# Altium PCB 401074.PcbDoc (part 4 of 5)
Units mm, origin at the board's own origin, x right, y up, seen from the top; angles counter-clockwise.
Board outline 70.15 x 35.15 mm, 6 copper layers (Top Layer, Mid-Layer1, Mid-Layer2, Mid-Layer3, Mid-Layer4, Bottom Layer), stack 1.549 mm thick; 239 components, 182 nets, 1034 pads, 1263 vias.
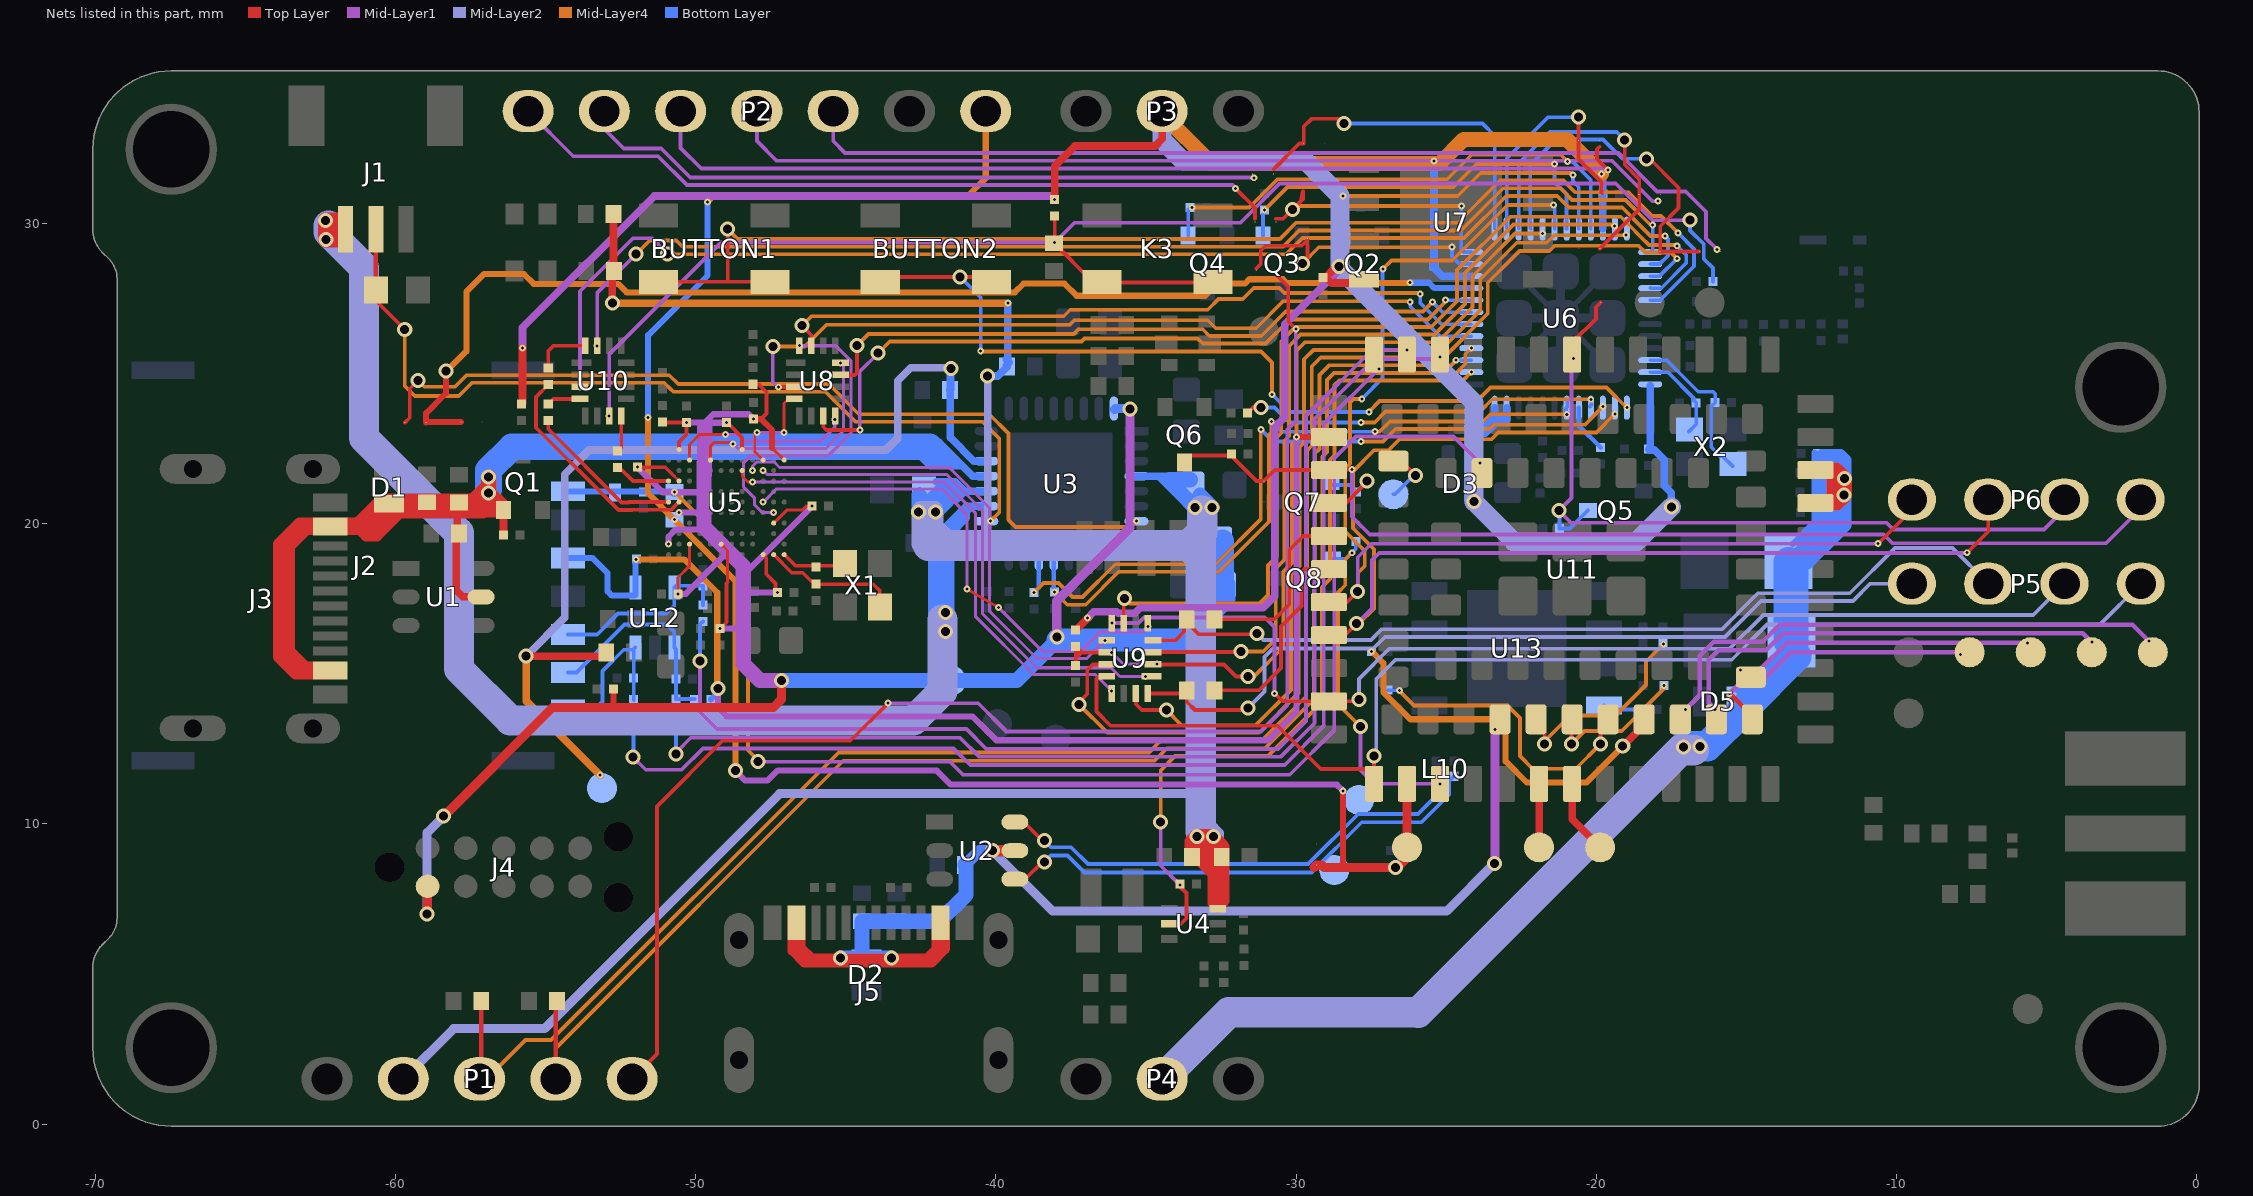
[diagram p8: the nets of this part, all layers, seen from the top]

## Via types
v1: diameter 0.23, hole 0.1, Top Layer to Mid-Layer1, tented both sides, 505 vias
v2: diameter 0.5, hole 0.3, Top Layer to Bottom Layer, tented both sides, 430 vias
v3: diameter 0.23, hole 0.1, Mid-Layer4 to Bottom Layer, tented both sides, 176 vias
v4: diameter 0.23/0.23 (per signal layer), hole 0.1, Mid-Layer4 to Bottom Layer, tented both sides, 144 vias
v5: diameter 0.5, hole 0.3, Top Layer to Bottom Layer, tented top, 7 vias
v6: diameter 0.4, hole 0.25, Top Layer to Bottom Layer, tented both sides, 1 vias

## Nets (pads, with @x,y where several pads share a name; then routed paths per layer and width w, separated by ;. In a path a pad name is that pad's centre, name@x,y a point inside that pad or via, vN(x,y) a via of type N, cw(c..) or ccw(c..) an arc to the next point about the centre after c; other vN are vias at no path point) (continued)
NetTP6_1: TP6.1 U11.101 | length 1.9
  Top Layer w0.127: U11.101@-26.757,22.079 -26.506,22.079 v2(-26.021,21.594)
  Bottom Layer w0.127: TP6.1@-26.763,20.973 -26.703,20.973 -26.082,21.594 v2(-26.021,21.594)
NetTP8_1: TP8.1 U11.104 | length 9.5
  Top Layer w0.152: v1(-15.562,14.344) -14.807,13.589 U11.104@-14.807,13.479
  Mid-Layer1 w0.152: v1(-15.562,14.344) -15.162,14.743 -14.488,14.743 -13.52,15.712 -7.946,15.712 v1(-7.879,15.644)
NetTP9_1: TP9.1 U11.105 | length 9.9
  Mid-Layer1 w0.152: v1(-15.196,15.124) -14.557,15.124 -13.652,16.03 -5.659,16.03 v1@-5.633,16.004
  other v1: -5.644,16.015
NetTP12_1: TP12.1 U11.29 | length 2.5
  Top Layer w0.254: U11.29@-20.807,11.329 -20.807,10.146 TP12.1@-19.875,9.214
NetTP13_1: TP13.1 U11.28 | length 2.1
  Top Layer w0.254: TP13.1@-21.907,9.214 U11.28@-21.907,11.329
NetTP14_1: TP14.1 U11.67 | length 15
  Mid-Layer1 w0.152: v1(-16.042,13.812) -16.256,14.026 -16.256,15.454 -15.935,15.776 -14.352,15.776 -13.78,16.348 -3.803,16.348 v1(-3.502,16.047)
NetTP15_1: TP15.1 U11.66 | length 17.6
  Mid-Layer1 w0.152: v1(-17.027,13.812) -16.561,14.278 -16.561,15.592 -16.098,16.055 -14.468,16.055 -13.895,16.627 -2.145,16.627 v1(-1.597,16.079)
NETWORK: Q7.G R53.1 U11.16 | length 3.1
  Top Layer w0.127: U11.16@-28.907,20.679 -28.344,20.679 -27.637,21.387 v2(-27.637,21.416)
  Bottom Layer w0.127: Q7.G@-28.864,21.279 -28.212,21.279 R53.1@-27.985,21.052 -27.637,21.4 v2(-27.637,21.416)
nRESET: C74.2 P6.4 Q6.C SB16.2 U11.15 | length 35.2
  Top Layer w0.127: Q6.C@-33.722,22.037 -33.499,22.26 -32.164,22.26 -31.32,21.416 SB16.2@-31.076,21.416 -30.713,21.779 U11.15@-28.907,21.779 ; U11.15@-28.907,21.794 v1(-28.139,21.794)
  Mid-Layer1 w0.127: v1(-28.139,21.794) -28.139,20.225 -27.546,19.633 -10.429,19.633 -10.138,19.341 -3.028,19.341 -1.871,20.498 P6.4@-1.871,20.794
nRF54_GPIO.P2.00: P1.5 SB8.1 | length 47.5
  Top Layer w0.127: P1.5@-52.115,1.265 P1.5@-52.115,1.5 -51.289,2.326 -51.289,10.58 -49.107,12.762 -44.85,12.762 v1(-43.596,14.015) ; -30.61,28.237 -30.615,28.232 -30.263,27.88 -30.263,26.731 v1(-30.01,26.478)
  Mid-Layer1 w0.127: v1(-43.596,14.015) -40.585,14.015 -39.643,13.072 -31.166,13.072 -30.299,13.94 -30.299,23.113 -30.01,23.401 v1(-30.01,26.478)
nRF54_GPIO.P2.01: P2.1 SB9.1 | length 25.9
  Top Layer w0.127: v1(-32.015,31.161) -31.37,30.516 -31.37,30.15
  Mid-Layer1 w0.127: P2.1@-55.578,33.735 -54.075,32.232 -51.249,32.232 -50.286,31.269 -32.123,31.269 v1(-32.015,31.161)
nRF54_GPIO.P2.02: P2.2 SB10.1 | length 22.9
  Mid-Layer1 w0.127: P2.2@-53.038,33.735 -53.038,33.13 -52.394,32.486 -51.143,32.486 -50.181,31.523 -31.409,31.523 v1(-31.4,31.514)
nRF54_GPIO.P2.03: P2.3 SB11.1 | length 33.4
  Top Layer w0.127: -19.891,32.55 -19.975,32.466 -19.975,32.141 v1(-19.611,31.777)
  Mid-Layer1 w0.127: P2.3@-50.498,33.735 -50.498,32.505 -49.812,31.819 -19.653,31.819 v1(-19.611,31.777)
nRF54_GPIO.P2.04: P2.4 SB12.1 | length 31.8
  Mid-Layer1 w0.127: P2.4@-47.958,33.735 -47.958,32.735 -47.306,32.082 -19.484,32.082 -18.136,30.734 v1(-17.944,30.734)
nRF54_GPIO.P2.05: P2.5 SB13.1 | length 32.5
  Mid-Layer1 w0.127: P2.5@-45.418,33.735 -45.418,32.735 -45.02,32.336 -19.255,32.336 -17.979,31.06 -17.026,31.06 -16.349,30.382 -16.349,29.493 v1(-15.977,29.121)
nRF54_PMIC.PMIC_GPIO: SB3.2 U3.7 | length 29.7
  Top Layer w0.127: SB3.2@-59.679,23.361 -59.52,23.52 -59.52,24.486 v2(-59.244,24.762)
  Mid-Layer4 w0.127: v2@-59.189,24.762 v2(-59.244,24.762) -59.038,24.556 -58.018,24.556 -57.635,24.939 -50.876,24.939 -50.579,24.642 -45.566,24.642 -44.565,23.64 -40.222,23.64 -39.577,22.996 -39.577,20.122 -39.343,19.887 -35.509,19.887 v4(-35.318,20.078)
nRF54_RESET: C37.2 K3.1 K3.2 R19.1 R23.2 U10.7 | length 50
  Top Layer w0.127: v1(-52.879,23.581) U10.7@-52.855,23.606 ; R19.1@-38.041,30.238 v1(-38.041,29.362) C37.2@-38.066,29.336 -36.779,28.05 K3.2@-36.472,28.05 -36.411,27.989 -36.369,28.031 -32.791,28.031 K3.1@-32.772,28.05
  Mid-Layer1 w0.127: v1(-52.879,23.581) -52.879,25.634 -49.153,29.359 -38.043,29.359 v1(-38.041,29.362) -37.385,30.017 -31.853,30.017 -30.55,31.32 -19.353,31.32 -18.134,30.1 v2(-16.889,30.1)
  Bottom Layer w0.127: v2@-16.879,30.011 -16.879,29.759 -16.424,29.303 -16.424,28.813 -16.116,28.506 R23.2@-16.116,28.053
nRF54_SWDCLK: U6.26 U10.3 | length 43
  Mid-Layer1 w0.127: v1(-53.848,24.55) -53.848,27.734 -52.081,29.5 -51.456,29.5 v2(-50.929,28.973)
  Mid-Layer4 w0.127: v2(-50.929,28.973) -50.921,28.965 -30.332,28.965 -29.789,29.509 -24.406,29.509 -23.004,30.91 -21.302,30.91 -20.917,30.525 -19.14,30.525 -18.428,29.813 -18.428,29.809 -18.249,29.63 -18.245,29.63 -18.195,29.58 v4(-17.716,29.58)
  Bottom Layer w0.127: U6.26@-18.207,28.637 -17.896,28.637 -17.616,28.917 -17.616,29.48 v4(-17.716,29.58)
nRF54_SWDIO: U6.25 U10.15 | length 40
  Mid-Layer1 w0.127: v1(-53.279,25.918) -53.279,27.679 v2(-51.978,28.98)
  Mid-Layer4 w0.127: v2(-51.978,28.98) -51.529,29.429 -50.648,29.429 -50.438,29.219 -30.437,29.219 -29.894,29.763 -24.511,29.763 -23.109,31.164 -21.197,31.164 -20.812,30.779 -19.035,30.779 -18.192,29.936 v3(-18.123,29.936)
  Bottom Layer w0.127: U6.25@-18.207,29.037 -18.123,29.121 v3(-18.123,29.936)
nRF93_LDO_OUT: C67.2 P2.7 R38.1 SB15.2 TP7.1 U11.24 | length 62.4
  Top Layer w0.203: -28.484,8.625 -28.433,8.676 v1(-28.433,11.094)
  Top Layer w0.305: -29.405,8.54 SB15.2@-29.32,8.625 -29.146,8.625 -29.06,8.54 v2(-26.694,8.54) ; v2@-26.631,8.54 -26.307,8.864 TP7.1@-26.307,9.214 U11.24@-26.307,11.329
  Mid-Layer1 w0.203: v2(-48.678,11.77) -48.348,11.439 -47.609,11.439 -47.279,11.77 -41.969,11.77 -41.504,11.305 -28.644,11.305 v1(-28.433,11.094)
  Mid-Layer4 w0.203: v3(-51.585,23.532) -51.585,21.002 v3(-50.709,20.126) -48.666,18.083 v2@-48.666,11.907 ; v3(-49.602,30.713) -49.39,30.925 -40.911,30.925 -40.338,31.498 P2.7@-40.338,33.735
  Bottom Layer w0.203: v3(-51.585,23.532) -51.585,26.276 -49.602,28.259 v3(-49.602,30.713)
  Bottom Layer w0.305: v2(-26.694,8.54) -26.3,8.934 C67.2@-26.3,9.113
nRF93_VBUS: C4.2 C5.2 C6.2 D2.K J5.A4 J5.A9 J5.B4 J5.B9 U2.5 U11.61 | length 46
  Top Layer w0.305: J5.A4@-46.787,6.741 -46.787,5.767 -46.383,5.363 -42.143,5.363 -41.687,5.819 J5.A9@-41.687,6.741 ; J5.B9@-46.487,6.741 -46.487,5.875 -46.14,5.527 v2(-45.177,5.527) v2(-43.478,5.527) -42.287,5.527 -41.987,5.827 J5.B4@-41.987,6.741
  Top Layer w0.381: v2(-40.119,9.102) U2.5@-39.37,9.102
  Mid-Layer1 w0.305: v2(-23.401,8.677) -23.377,8.701 v1(-23.377,13.134)
  Mid-Layer2 w0.305: v2(-40.119,9.102) -38.108,7.092 -24.987,7.092 v2(-23.401,8.677)
  Bottom Layer w0.381: C6.2@-41.024,8.632 -40.554,9.102 v2(-40.119,9.102)
  Bottom Layer w0.508: v2(-45.177,5.527) -44.458,5.527 C4.2@-44.458,6.756 C5.2@-43.369,6.756 ; D2.K@-44.292,5.527 v2(-43.478,5.527) ; C5.2@-43.315,6.754 -41.877,6.754 -40.998,7.634 -40.998,8.606 -41.024,8.632 C6.2@-41.026,8.632
NTC: J1.2 R1.2 U3.18 | length 29.5
  Top Layer w0.127: R1.2@-60.653,27.917 R1.2@-60.653,27.776 -60.653,27.431 v2(-59.688,26.466)
  Top Layer w0.152: J1.2@-60.653,29.805 -60.653,28.088 R1.2@-60.481,27.916
  Mid-Layer4 w0.127: v2(-59.688,26.466) -59.688,24.583 -59.355,24.25 -57.889,24.25 -57.454,24.685 -51.043,24.685 -50.825,24.467 -50.746,24.388 -45.672,24.388 -44.67,23.386 -40.446,23.386 -39.888,22.829 -39.888,20.367 v4(-40.177,20.078)
P0.00: U6.23 U9.3 | length 27.4
  Top Layer w0.127: U9.3@-34.769,15.709 -34.754,15.724 -31.856,15.724 v2(-31.841,15.739)
  Mid-Layer4 w0.127: v2(-31.841,15.739) -31.836,15.734 -31.094,15.734 -30.681,16.148 -30.681,18.501 -30.395,18.786 -30.395,22.752 -30.242,22.905 -30.242,25.903 -29.854,26.291 -25.393,26.291 -24.378,27.306 -24.378,28.342 -22.759,29.961 -19.449,29.961 v3(-19.393,29.904)
P0.01: U6.24 U9.15 | length 30.5
  Top Layer w0.127: U9.15@-35.338,14.34 -35.338,13.981 -35.14,13.784 v2(-34.316,13.784)
  Mid-Layer4 w0.127: v2(-34.316,13.784) -33.814,13.282 -31.348,13.282 -30.173,14.458 -30.173,18.29 -29.887,18.576 -29.887,22.541 -29.734,22.694 -29.734,25.47 -29.422,25.783 -25.183,25.783 -23.87,27.095 -23.87,28.132 -22.652,29.35 -21.661,29.35 -21.412,29.599 -19.018,29.599 v3(-19.012,29.605)
P0.02: U6.27 U9.11 | length 37.1
  Top Layer w0.127: v2(-37.236,13.977) -37.236,14.044 -36.959,14.322 -36.959,15.116 -36.766,15.309 U9.11@-36.306,15.309
  Mid-Layer4 w0.127: v2(-37.236,13.977) -37.234,13.977 -36.285,13.028 -31.243,13.028 -29.919,14.352 -29.919,18.185 -29.633,18.47 -29.633,22.436 -29.48,22.589 -29.48,25.227 -29.179,25.529 -25.077,25.529 -23.616,26.99 -23.616,28.027 -22.562,29.08 -21.571,29.08 -21.399,29.252 -18.592,29.252 -18.36,29.02 -17.513,29.02 v4(-17.31,28.818)
  Bottom Layer w0.127: U6.27@-18.207,28.237 -17.896,28.237 -17.315,28.818 v4(-17.31,28.818)
P0.03: U6.28 U9.7 | length 32.6
  Top Layer w0.127: U9.7@-35.738,16.677 -35.738,17.484 v2(-35.712,17.51)
  Mid-Layer4 w0.127: v2(-35.712,17.51) -35.535,17.332 -31.225,17.332 -30.937,17.62 -30.937,18.603 -30.649,18.891 -30.649,22.857 -30.496,23.01 -30.496,26.066 -30.018,26.545 -25.498,26.545 -24.64,27.403 -24.64,28.439 -22.864,30.215 -19.189,30.215 -18.706,29.732 -18.706,29.728 -18.355,29.376 -18.351,29.376 -18.249,29.274 -17.335,29.274 v4(-17.31,29.25)
  Bottom Layer w0.127: U6.28@-18.193,27.851 U6.28@-18.207,27.837 -17.839,27.837 -17.005,28.672 -17.005,28.944 v4(-17.31,29.25)
P0.04: BUTTON1.1 BUTTON1.2 U6.29 | length 42.2
  Top Layer w0.127: BUTTON1.2@-51.229,28.05 -48.932,28.05 ; v2(-48.932,29.8) -48.932,28.05 ; BUTTON1.1@-47.311,28.05 BUTTON1.1@-47.529,28.05 -48.932,28.05
  Mid-Layer4 w0.127: v2(-48.932,29.8) -48.605,29.473 -48.232,29.473 -30.979,29.473 -30.543,29.473 -29.999,30.017 -24.616,30.017 -23.215,31.418 -21.092,31.418 -20.707,31.033 -18.93,31.033 -18.143,30.246 -17.849,30.246 v4(-17.285,29.682)
  Bottom Layer w0.127: U6.29@-18.207,27.437 -17.88,27.437 -16.751,28.567 -16.751,29.147 v4(-17.285,29.682)
P1.01/XL2: R10.2 U4.5 U6.2 | length 27.7
  Top Layer w0.127: U4.5@-34.218,6.661 -33.845,6.661 -33.655,6.851 -33.655,7.688 -33.864,7.897 v1(-33.864,7.955)
  Mid-Layer1 w0.127: v2(-34.511,10.053) -34.511,8.601 v1(-33.864,7.955)
  Mid-Layer4 w0.127: v2(-34.511,10.053) -34.511,11.773 -34.03,12.254 -30.939,12.254 -29.136,14.057 -29.136,17.89 -28.871,18.155 -28.871,22.12 -28.718,22.273 -28.718,24.607 -28.566,24.759 -24.445,24.759 v3(-24.167,25.037)
P1.02/NFC1: C55.2 P1.3 U6.3 | length 51.7
  Top Layer w0.152: P1.3@-57.195,1.5 -57.14,1.555 C55.2@-57.14,4.1
  Mid-Layer4 w0.127: P1.3@-57.195,1.265 -55.666,2.794 -54.817,2.794 -45.234,12.377 -34.897,12.377 -34.513,12.762 -31.15,12.762 -29.665,14.247 -29.665,18.08 -29.379,18.365 -29.379,22.331 -29.226,22.484 -29.226,24.95 -28.909,25.267 -24.842,25.267 v3(-24.672,25.437)
  Bottom Layer w0.127: v3(-24.672,25.437) U6.3@-24.167,25.437
P1.03/NFC2: C56.1 P1.4 U6.4 | length 50
  Top Layer w0.152: P1.4@-54.655,1.5 -54.655,4.065 C56.1@-54.621,4.1
  Mid-Layer4 w0.127: P1.4@-54.655,1.5 -54.655,2.526 -45.084,12.097 -34.721,12.097 -34.31,12.508 -31.045,12.508 -29.411,14.142 -29.411,17.975 -29.125,18.26 -29.125,22.226 -28.972,22.379 -28.972,24.784 -28.743,25.013 -24.664,25.013 -24.367,25.311 -24.367,25.638 v3(-24.167,25.837)
P1.04: U6.5 U8.3 | length 26.6
  Top Layer w0.127: v1(-47.246,24.539) -47.235,24.55 U8.3@-46.716,24.55
  Mid-Layer1 w0.127: v2(-47.429,25.891) -47.429,24.722 v1(-47.246,24.539)
  Mid-Layer4 w0.127: v2(-47.429,25.891) -46.367,25.891 -45.64,26.619 -37.541,26.619 -37.389,26.772 -32.946,26.772 -32.677,26.503 -31.33,26.503 -30.434,27.399 -26.229,27.399 v3(-26.2,27.37)
  Bottom Layer w0.127: v3(-26.2,27.37) -26.2,27.226 -25.211,26.237 U6.5@-24.167,26.237
P1.05: U6.6 U8.15 | length 24.3
  Top Layer w0.127: v2(-46.452,26.588) -46.147,26.283 U8.15@-46.147,25.919
  Mid-Layer4 w0.127: v2(-46.452,26.588) -46.139,26.901 -37.738,26.901 -37.521,27.119 -32.944,27.119 -32.588,27.475 -31.778,27.475 -31.412,27.841 -30.562,27.841 -30.397,27.676 -25.895,27.676 v3(-25.867,27.648)
  Bottom Layer w0.127: v3(-25.867,27.648) -25.867,27.346 -25.158,26.637 U6.6@-24.167,26.637
P1.06: U6.7 U8.11 | length 22.9
  Top Layer w0.127: U8.11@-45.179,24.95 -44.698,24.95 -44.626,25.021 v2(-44.626,25.925)
  Mid-Layer4 w0.127: v2(-44.626,25.925) -44.241,26.31 -37.403,26.31 -37.247,26.467 -33.111,26.467 -32.893,26.249 -31.163,26.249 -30.347,27.065 -25.778,27.065 v3(-25.463,27.379)
  Bottom Layer w0.127: v3(-25.463,27.379) -25.122,27.037 U6.7@-24.167,27.037
P1.07: U6.8 U8.7 | length 25.1
  Top Layer w0.127: U8.7@-45.747,23.582 -45.747,23.22 -45.637,23.11 v1(-44.532,23.11)
  Mid-Layer1 w0.127: v1(-44.532,23.11) -44.532,25.058 v2(-43.918,25.671)
  Mid-Layer4 w0.127: v2(-43.918,25.671) -43.533,26.056 -37.153,26.056 -37.047,26.162 -33.279,26.162 -33.112,25.995 -31.014,25.995 -30.211,26.799 -25.612,26.799 -25.032,27.379 v3(-25.032,27.443)
  Bottom Layer w0.127: v3(-25.032,27.443) -25.026,27.437 U6.8@-24.167,27.437
P1.08: SB2.2 SB3.1 U6.9 | length 40.7
  Top Layer w0.203: v2(-58.313,25.082) -58.313,24.338 -58.979,23.672 SB3.1@-58.979,23.361 -58.961,23.379 SB2.2@-57.818,23.379
  Mid-Layer4 w0.203: v2(-58.313,25.082) -58.284,25.082 -57.632,25.735 -57.632,27.725 -57.051,28.305 -55.716,28.305 -55.391,27.98 -52.58,27.98 -52.296,27.697 -39.37,27.697 -39.074,27.993 -37.719,27.993 -37.31,27.584 -33.034,27.584 -32.625,27.993 -31.699,27.993 -31.559,28.133 -30.441,28.133 -30.322,28.014 -26.206,28.014 v3(-26.202,28.018)
  Bottom Layer w0.203: v3(-26.202,28.018) -25.575,28.018 -25.394,27.837 U6.9@-24.167,27.837
P1.09: BUTTON2.1 BUTTON2.2 U6.37 | length 30.2
  Top Layer w0.127: BUTTON2.2@-43.85,28.05 -43.695,28.206 v2(-41.188,28.206) -40.306,28.206 BUTTON2.1@-40.15,28.05
  Mid-Layer4 w0.127: v3(-40.504,25.751) -40.48,25.727 -31.172,25.727 -30.802,25.357 v3(-30.802,24.302) ; v3(-27.579,23.718) -27.222,24.075 -23.98,24.075 -23.526,24.529 -19.659,24.529 v4(-18.987,23.857)
  Bottom Layer w0.127: v2(-41.188,28.206) -40.504,27.522 v3(-40.504,25.751) ; v3(-30.802,24.302) -30.217,23.718 v3(-27.579,23.718)
P1.10: P6.2 U6.38 U11.20 | length 40.5
  Top Layer w0.127: U11.20@-28.907,16.279 -28.367,16.279 v2(-27.984,16.663) ; v1(-7.654,19.026) -6.951,19.729 P6.2@-6.951,20.794
  Mid-Layer1 w0.127: v2(-27.984,16.663) -27.472,17.174 -27.472,18.78 -27.23,19.022 -7.658,19.022 v1(-7.654,19.026)
  Mid-Layer4 w0.127: v2(-27.984,16.663) -27.912,16.663 -27.409,17.165 -27.409,19.142 -28.109,19.842 -28.109,21.733 -27.403,22.439 -26.923,22.439 -26.554,22.808 -23.497,22.808 -23.273,23.032 -20,23.032 v3(-19.387,23.645)
P1.11: R7.1 U3.14 U6.39 | length 25.2
  Mid-Layer4 w0.127: v3(-38.727,17.708) -38.417,18.018 -37.914,18.018 -37.735,17.839 -37.446,17.549 -37.118,17.549 -36.022,18.645 -32.677,18.645 -31.175,20.147 v3(-31.175,23.134) ; v3(-27.838,22.733) -27.104,22.733 -26.691,23.146 -23.568,23.146 -23.428,23.286 -20.382,23.286 v3(-19.777,23.891)
  Bottom Layer w0.127: v3(-31.175,23.134) -30.775,22.733 v3(-27.838,22.733)
  Bottom Layer w0.152: v3(-38.727,17.708) -38.568,17.866 U3.14@-38.568,18.828
P1.12: R44.1 U6.40 | length 12.3
  Top Layer w0.127: R44.1@-31.623,23.682 -31.441,23.864 v2(-31.166,23.864)
  Mid-Layer4 w0.127: v2@-31.276,23.709 -31.166,23.819 v2(-31.166,23.864) ; v3(-27.833,23.362) -27.381,23.363 -27.018,23.726 -23.881,23.726 -23.47,24.137 v3(-20.187,24.137)
  Bottom Layer w0.127: v2(-31.166,23.864) -30.723,23.864 -30.221,23.362 v3(-27.833,23.362) ; U6.40@-20.207,23.896 -20.152,23.952 U6.40@-20.166,23.967
P1.13: R43.1 U6.41 | length 1.6
  Bottom Layer w0.152: U6.41@-20.587,23.857 -20.587,23.26 R43.1@-19.857,22.53
P1.14: R8.2 U3.13 U6.42 | length 23.6
  Mid-Layer4 w0.127: v3(-38.041,17.712) -37.624,17.295 -37.006,17.295 -35.91,18.391 -32.572,18.391 -30.903,20.06 -30.903,22.962 -30.828,23.037 v3(-30.828,23.402) ; v3(-27.373,23.057) -27.218,23.057 -26.876,23.4 -23.77,23.4 -23.533,23.637 v3@-21.008,23.637
  Bottom Layer w0.127: v3(-30.828,23.402) -30.484,23.057 -27.96,23.057 ; -27.96,23.057 v3(-27.373,23.057) ; U6.42@-21.008,23.637 -21.008,23.836 U6.42@-20.987,23.857 -20.972,23.872 U6.42@-20.972,24.087
  Bottom Layer w0.152: R8.2@-38.068,17.712 U3.13@-38.068,18.828
  other v3: -20.987,23.637
P2.00: SB8.2 SB22.1 U6.11 | length 9.4
  Top Layer w0.127: -31.326,28.493 -31.177,28.641 -31.177,29.088 -31.012,29.253 -29.814,29.253 -29.648,29.418 ; v2(-29.789,28.659) -29.619,28.829 -29.619,29.447
  Mid-Layer4 w0.127: v2(-29.789,28.659) -29.245,29.203 v3(-24.807,29.203)
  Bottom Layer w0.127: v3(-24.807,29.203) -24.807,28.891 -24.553,28.637 U6.11@-24.167,28.637
P2.01: SB9.2 SB18.1 U6.12 | length 9
  Top Layer w0.127: -30.67,30.15 -30.432,30.15 v2(-30.121,30.461) -29.84,30.742 ; -29.84,30.742 -29.772,30.81 SB18.1@-29.772,31.067 -29.84,30.742
  Mid-Layer4 w0.127: v2@-29.944,30.569 v3(-24.496,30.569)
  Bottom Layer w0.127: v3(-24.496,30.569) -24.502,30.55 -24.502,29.123 -24.416,29.037 U6.12@-24.167,29.037
P2.02: SB10.2 SB19.1 U6.13 | length 11.7
  Top Layer w0.127: -30.758,31.795 -29.898,32.655 SB19.1@-29.747,32.655 -29.747,33.219 -29.489,33.477 -28.566,33.477 v2(-28.413,33.324)
  Bottom Layer w0.127: v2(-28.413,33.324) -23.794,33.324 -23.387,32.916 U6.13@-23.387,29.817
P2.03: SB11.2 SB21.1 U6.14 | length 8.2
  Top Layer w0.127: v2(-20.594,33.546) -20.594,32.553 -20.591,32.55 -20.591,32.14 -19.826,31.375 -19.826,30.994
  Bottom Layer w0.127: U6.14@-22.987,29.817 -22.987,32.153 -21.609,33.531 v2@-20.594,33.531
P2.04: SB12.2 SB20.1 U6.15 | length 10.6
  Top Layer w0.127: SB20.1@-19.875,29.16 -18.575,30.46 SB12.2@-18.575,30.96 -18.575,31.466 -19.056,31.947 v2(-19.056,32.779)
  Bottom Layer w0.127: U6.15@-22.587,29.817 -22.587,32.011 -21.554,33.044 -19.321,33.044 v2(-19.056,32.779)
P2.05: SB13.2 SB17.1 U6.16 | length 11.8
  Top Layer w0.127: v2(-18.325,32.147) -18.225,32.147 -17.373,31.295 -17.26,31.181 -17.26,31.119 -17.26,30.512 -17.875,29.897 SB17.1@-17.875,29.06 SB13.2@-16.575,29.06
  Bottom Layer w0.127: U6.16@-22.187,29.817 -22.202,29.832 -22.202,31.934 -21.346,32.79 -19.777,32.79 -19.134,32.147 v2(-18.325,32.147)
P2.06: R20.2 R21.2 U6.17 U9.2 U9.10 | length 29.4
  Top Layer w0.127: R20.2@-37.342,15.272 -37.342,15.516 ; -37.287,15.628 R21.2@-37.287,15.845 ; R21.2@-37.287,15.9 R21.2@-37.287,15.845 ; U9.10@-36.306,15.709 -37.15,15.709 ; U9.2@-34.769,15.309 -34.638,15.309 -32.401,15.309 -31.997,14.905 v2(-31.61,14.905) ; -37.342,15.516 -37.15,15.709 ; -37.342,15.516 R21.2@-37.342,15.901 R21.2@-37.287,15.845 ; R21.2@-37.287,15.845 -37.15,15.709
  Mid-Layer1 w0.102: v1@-36.146,15.714 -35.746,15.315 v1(-34.638,15.315)
  Mid-Layer4 w0.127: v2(-31.61,14.905) -31.401,14.905 -30.427,15.88 -30.427,18.396 -30.141,18.681 -30.141,22.646 -29.988,22.8 -29.988,25.758 -29.709,26.037 -25.288,26.037 -24.124,27.2 -24.124,28.237 -22.705,29.655 v3(-21.787,29.655)
  other v1: -36.146,15.709
P2.07: P6.1 U6.18 U11.19 | length 40.8
  Top Layer w0.127: U11.19@-28.907,17.379 -28.305,17.379 v2(-27.95,17.735) ; v1(-10.619,19.327) -9.491,20.455 P6.1@-9.491,20.794
  Mid-Layer1 w0.127: v2(-27.95,17.735) -27.95,18.876 -27.499,19.327 v1(-10.619,19.327)
  Mid-Layer4 w0.127: v2(-27.95,17.735) -27.95,18.344 -27.715,18.58 -27.715,19.088 -28.363,19.737 -28.363,21.838 -28.21,21.991 -28.21,24.02 -28.08,24.15 v3(-27.814,24.15) ; v3(-27.113,28.471) -26.828,28.755 -24.8,28.755 -22.95,30.605 v3(-21.429,30.605)
  Bottom Layer w0.127: v3(-27.814,24.15) -27.119,24.845 v3@-27.119,28.471 ; v3(-21.429,30.605) -21.387,30.563 U6.18@-21.387,29.817
P2.08: Q3.G R28.1 U6.19 | length 13.5
  Mid-Layer4 w0.127: v3(-31.056,30.441) -30.285,31.211 -24.762,31.211 -23.996,31.978 v3(-21.39,31.978)
  Bottom Layer w0.127: Q3.G@-31.105,29.584 -31.105,30.298 R28.1@-31.005,30.398 ; v3(-21.39,31.978) -21.39,31.361 -20.997,30.969 -20.997,29.828 U6.19@-20.987,29.817
P2.09: Q2.G R27.1 U6.20 | length 11.2
  Mid-Layer4 w0.127: v3(-28.433,30.906) -24.615,30.906 -23.849,31.672 -20.847,31.672 v3(-20.776,31.601)
  Bottom Layer w0.127: Q2.G@-28.433,29.584 v3(-28.433,30.906) ; v3(-20.776,31.601) -20.776,31.387 -20.587,31.198 U6.20@-20.587,29.817
P2.10: Q4.G R29.1 U6.21 | length 17
  Mid-Layer4 w0.127: v3(-33.469,30.525) -31.564,30.525 -30.623,31.465 -24.971,31.465 -24.153,32.283 -21.189,32.283 v3(-20.958,32.053)
  Bottom Layer w0.127: Q4.G@-33.595,29.584 -33.595,30.464 R29.1@-33.533,30.525 ; v3@-20.958,32.044 v3(-20.958,32.053) -20.795,32.053 -20.187,31.444 U6.21@-20.187,29.817
POWERKEY: C73.2 P6.3 Q5.C SB1.2 U11.7 | length 26.9
  Top Layer w0.127: U11.7@-20.807,25.629 -20.807,26.022 -20.015,26.814 -20.015,27.2 SB1.2@-19.855,27.36
  Mid-Layer1 w0.127: v1(-20.761,25.498) -20.832,25.426 -20.832,20.854 v2(-21.251,20.436) -20.838,20.022 -10.332,20.022 -10.113,19.804 -5.091,19.804 -4.411,20.484 P6.3@-4.411,20.794
  Bottom Layer w0.127: v2@-21.295,20.392 -21.227,20.323 C73.2@-21.227,19.829 -20.885,19.829 Q5.C@-20.274,20.44
SIM1_CLK: R40.1 U11.13 | length 38.3
  Mid-Layer1 w0.127: v2(-52.092,12.225) -51.663,11.796 -50.468,11.796 -49.757,12.508 -41.406,12.508 -40.854,11.956 -30.377,11.956 -29.083,13.25 -29.083,23.311 v1(-27.242,25.152)
  Bottom Layer w0.127: v2(-52.092,12.225) -52.066,12.252 R40.1@-52.066,13.596
SIM1_DET: C68.1 D7.A J2.CD R38.2 U11.79 | length 48.3
  Mid-Layer1 w0.127: v2(-47.93,12.067) -41.529,12.067 -41.096,11.634 -30.21,11.634 -28.727,13.117 -28.727,22.184 -28.009,22.902 -24.763,22.902 v1(-23.878,22.016)
  Mid-Layer4 w0.127: v3(-50.709,21.051) -48.253,18.595 -48.253,12.449 v2@-47.864,12.06
  Bottom Layer w0.203: J2.CD@-54.257,21.067 -50.797,21.067 R38.2@-50.709,20.979
SIM1_IO: R42.2 U11.11 | length 38.6
  Mid-Layer1 w0.127: v2@-50.721,12.432 -50.592,12.432 -50.162,12.862 -41.192,12.862 -40.565,12.234 -30.499,12.234 -29.388,13.346 -29.388,23.487 -27.396,25.479 -25.278,25.479 v1(-25.207,25.55)
  Bottom Layer w0.127: v2@-50.721,12.432 -50.65,12.503 R42.2@-50.65,13.6
  other v2: -50.657,12.322
SIM1_RST: R41.1 U11.12 | length 38.6
  Mid-Layer1 w0.127: v2(-49.85,15.419) -49.85,13.722 -49.28,13.151 -40.981,13.151 -40.319,12.488 -30.605,12.488 -29.667,13.426 -29.667,23.58 -27.463,25.784 v1(-26.311,25.784)
  Bottom Layer w0.127: v2(-49.85,15.419) -49.85,16.644 R41.1@-49.759,16.736
SIM1_VOUT: C71.2 J2.1 R39.2 U11.14 U12.4 | length 42.1
  Top Layer w0.203: v1(-29.993,22.88) U11.14@-28.907,22.879
  Mid-Layer1 w0.203: v2(-49.252,14.503) -49.252,13.861 -48.963,13.573 -40.781,13.573 -39.988,12.78 -30.934,12.78 -29.993,13.721 v1(-29.993,22.88)
  Mid-Layer4 w0.203: v3(-51.978,18.803) -50.381,18.803 -49.28,17.702 -49.28,14.531 v2(-49.252,14.503)
  Bottom Layer w0.203: J2.1@-54.257,18.847 -53.431,18.847 -52.934,18.35 -52.934,17.743 -52.789,17.598 U12.4@-52.029,17.598 ; U12.4@-52.009,17.619 U12.4@-52.009,17.867 -52.009,18.714 C71.2@-51.918,18.805 ; R39.2@-49.488,14.146 -49.252,14.382 v2(-49.252,14.503)
SIM2_CLK: R52.2 U11.62 | length 6.8
  Top Layer w0.127: U11.62@-22.007,13.479 -21.721,13.193 v2(-21.721,12.649)
  Mid-Layer4 w0.127: v2(-21.721,12.649) -21.721,12.751 -20.87,13.601 -19.365,13.601 -18.35,14.616 -18.35,15.396 v4(-17.766,15.979)
SIM2_IO: R51.1 U11.64 | length 10.2
  Top Layer w0.127: v2(-19.866,12.653) -19.866,13.22 U11.64@-19.607,13.479
  Mid-Layer4 w0.127: v4(-26.557,14.436) -26.557,14.418 -26.076,13.937 -22.961,13.937 -22.545,13.521 -22.545,12.253 -22.123,11.832 -20.687,11.832 v2(-19.866,12.653)
  Bottom Layer w0.127: R51.1@-26.942,14.447 -26.567,14.447 v4(-26.557,14.436)
SIM2_RST: R50.2 U11.63 | length 4.8
  Top Layer w0.127: v2(-20.832,12.657) -20.832,13.453 U11.63@-20.807,13.479
  Mid-Layer4 w0.127: v2(-20.832,12.657) -20.396,13.093 -19.154,13.093 -17.749,14.499 v4(-17.749,14.604)
SIM2_VOUT: C76.2 R49.2 U11.65 U13.8@-19.751,13.937 | length 15.9
  Top Layer w0.254: v2(-19.122,12.586) -18.63,13.078 -18.63,13.256 U11.65@-18.407,13.479
  Mid-Layer4 w0.203: v4(-27.488,15.74) -27.092,15.344 -27.092,14.375 -26.196,13.479 -23.229,13.479 -23.022,13.272 -23.022,12.083 -22.31,11.372 -20.336,11.372 v2(-19.122,12.586)
  Bottom Layer w0.127: U13.8@-19.751,13.937 -19.62,13.806 C76.2@-18.539,13.806 -18.539,13.169 v2(-19.122,12.586)
SIM_CLK: C69.2 J2.3 R40.2 U12.3 | length 5.4
  Bottom Layer w0.127: J2.3@-54.257,13.767 -53.405,13.767 -53.106,14.066 -53.106,15.082 -52.393,15.794 -52.082,15.794 U12.3@-52.058,15.818 ; R40.2@-52.058,14.111 U12.3@-52.058,15.818 ; U12.3@-52.009,15.867 U12.3@-52.058,15.818
SIM_DATA: C72.2 J2.7 R39.1 R42.1 U12.1 | length 7.2
  Bottom Layer w0.127: J2.7@-54.257,15.037 -53.969,15.037 -52.37,16.636 -50.963,16.636 -50.709,16.382 U12.1@-50.709,15.867 -50.65,15.809 C72.2@-50.65,14.823 R42.1@-50.65,14.15 -50.042,14.15 R39.1@-50.038,14.146
SIM_RST: C70.2 J2.2 R41.2 U12.5 | length 6.2
  Bottom Layer w0.127: J2.2@-54.257,16.307 -53.278,16.307 -52.588,16.997 -50.98,16.997 -50.709,17.269 U12.5@-50.709,17.867 -50.65,17.926 C70.2@-49.759,17.926 R41.2@-49.759,17.286
STATUS: Q8.G R54.1 U11.25 | length 11.8
  Mid-Layer1 w0.127: v2(-27.859,13.232) -27.859,11.789 -27.399,11.329 v1(-25.207,11.329)
  Mid-Layer4 w0.127: v3(-28.145,19.024) -28.363,18.806 -28.363,17.944 -28.604,17.703 -28.604,13.978 v2(-27.859,13.232)
  Bottom Layer w0.127: Q8.G@-28.811,18.825 -28.344,18.825 v3(-28.145,19.024) -28.012,19.158 R54.1@-28.012,19.402
SWD3_CLK: R16.1 U5.F12 | length 5.3
  Top Layer w0.127: R16.1@-54.908,23.431 -54.908,23.143 -52.468,20.703 -52.226,20.703 -52.217,20.712 U5.F12@-50.9,20.712
SWD3_IO: R14.1 U5.F11 | length 7.6
  Top Layer w0.127: R14.1@-54.908,24.622 -55.314,24.215 -55.314,23.19 -52.574,20.449 -52.121,20.449 -52.112,20.458 -50.805,20.458 -50.805,20.468 -50.561,20.712 U5.F11@-50.55,20.712
SWD3_nRF5340.RESET: R18.2 U10.8 | length 1.2
  Top Layer w0.127: R18.2@-52.597,22.418 -52.479,22.535 U10.8@-52.479,23.581
SWD3_nRF5340.SWDCLK: R16.2 U10.4 | length 1.1
  Top Layer w0.127: R16.2@-54.908,23.981 -54.739,24.15 U10.4@-53.848,24.15
SWD3_nRF5340.SWDIO: R14.2 U10.16 | length 1.9
  Top Layer w0.127: R14.2@-54.908,25.172 -54.908,25.742 -54.731,25.918 U10.16@-53.679,25.918
SWD3_RESET: R18.1 U5.H12 | length 1.9
  Top Layer w0.127: R18.1@-52.597,21.868 -52.544,21.868 -52.088,21.412 U5.H12@-50.9,21.412
UART1_CTS: P5.4 U9.12 U11.23 | length 41.8
  Top Layer w0.127: U9.12@-36.306,14.909 -36.573,14.909 -36.652,14.83 -36.652,13.737 -36.179,13.264 -30.62,13.264 -29.181,11.825 U11.23@-27.407,11.825 ; U11.23@-27.407,11.318 -27.407,11.64 U11.23@-27.407,11.825 ; v2(-27.407,12.259) U11.23@-27.407,11.825
  Mid-Layer2 w0.127: v2(-27.407,12.259) -27.332,12.334 -27.332,14.824 -26.696,15.46 -15.493,15.46 -14.319,16.634 -3.231,16.634 P5.4@-1.871,17.994
UART1_nRF93.RXD: P5.2 R63.1 U9.4 | length 30.4
  Top Layer w0.127: U9.4@-34.769,16.109 -34.02,16.109 -33.736,16.393 -33.736,16.611 R63.1@-33.642,16.705 ; R63.1@-33.642,16.809 R63.1@-33.642,16.705 ; v2(-31.306,16.337) -31.334,16.309 -33.247,16.309 R63.1@-33.642,16.705
  Mid-Layer2 w0.127: v2@-31.264,16.337 v2(-31.306,16.337) -31.088,16.118 -27.511,16.118 -27.152,16.477 -15.82,16.477 -14.622,17.674 -11.562,17.674 -10.057,19.179 -8.136,19.179 P5.2@-6.951,17.994
UART1_nRF93.TXD: P5.1 R62.1 U9.16 | length 28.4
  Top Layer w0.127: U9.16@-34.938,14.34 -33.746,14.34 R62.1@-33.641,14.444 -33.641,14.062 -33.363,13.784 -31.674,13.784 v2(-31.604,13.854)
  Mid-Layer2 w0.127: v2(-31.604,13.854) -31.053,14.405 -31.053,15.559 -30.773,15.839 -27.431,15.839 -27.047,16.223 -15.712,16.223 -14.515,17.42 -11.457,17.42 -10.883,17.994 P5.1@-9.491,17.994
UART1_RTS: P5.3 U9.8 U11.22 | length 36.1
  Top Layer w0.127: v1(-30.724,14.344) -30.459,14.079 U11.22@-28.907,14.079 ; U11.22@-28.713,14.079 -27.972,14.079 v2(-27.909,14.142)
  Mid-Layer1 w0.127: v1@-36.124,16.689 -35.249,16.689 -35.065,16.873 -31.046,16.873 -30.724,16.551 v1(-30.724,14.344)
  Mid-Layer2 w0.127: v2(-27.909,14.142) -27.909,14.822 -26.906,15.826 -15.564,15.826 -14.434,16.956 -5.449,16.956 P5.3@-4.411,17.994
  other v1: -36.125,16.688
UART1_RXD: R63.2 U11.17 | length 6
  Top Layer w0.127: R63.2@-32.717,16.809 -30.715,16.809 -30.226,17.298 -30.226,19.116 -29.763,19.579 U11.17@-28.907,19.579
UART1_TXD: R62.2 U11.18 | length 7
  Top Layer w0.127: R62.2@-32.716,14.444 -31.239,14.444 -30.499,15.184 -30.499,16.567 -29.82,17.246 -29.82,18.377 -29.718,18.479 U11.18@-28.907,18.479
USB2_N: L10.3 TP11.1 U2.4 | length 16.4
  Top Layer w0.127: U2.4@-39.077,8.152 -39.024,8.152 v2@-38.452,8.724
  Bottom Layer w0.127: v2(-38.388,8.724) -38.172,8.94 -37.612,8.94 -37.048,8.376 -29.486,8.376 -27.813,10.049 -25.83,10.049 -24.9,10.979 -24.9,11.418 L10.3@-24.737,11.582
USB2_P: L10.2 TP10.1 U2.6 | length 16.3
  Top Layer w0.127: U2.6@-39.37,10.052 -39.069,10.052 v2@-38.452,9.435
  Bottom Layer w0.127: v2(-38.388,9.435) -38.172,9.219 -37.496,9.219 -36.932,8.656 -29.602,8.656 -27.929,10.329 -25.946,10.329 -25.18,11.095 -25.18,11.425 L10.2@-25.337,11.582
VBAT_PMIC: C11.2 J1.3 U3.19 | length 47.9
  Top Layer w0.508: v2@-62.328,29.453 -62.328,29.776 ; v2(-62.306,29.453) -62.051,29.453 ; J1.3@-61.745,29.453 -62.051,29.453 ; J1.3@-61.697,29.776 J1.3@-61.729,29.776 ; -62.328,29.776 v2(-62.328,30.098) -61.697,30.098 -61.693,30.094 -61.693,29.812 J1.3@-61.729,29.776 ; -62.328,29.776 J1.3@-61.729,29.776 ; -62.051,29.453 J1.3@-61.729,29.776
  Mid-Layer2 w1: v2@-62.23,29.916 -62.23,29.712 -61.048,28.53 -61.048,22.854 -57.887,19.692 -57.887,15.153 -56.179,13.446 -42.743,13.446 -41.783,14.406 -41.783,16.809
  Bottom Layer w0.254: C11.2@-41.952,19.61 -40.984,20.578 ; C11.2@-41.814,19.345 -41.814,19.554 -41.495,19.873 ; C11.2@-41.7,19.47 -41.495,19.675 ; -41.495,19.3 -41.495,19.675 ; U3.19@-40.318,20.578 -40.79,20.578 ; -41.495,19.675 -40.984,20.186 -40.984,20.384 ; -41.495,19.675 -41.495,19.873 ; -41.495,19.873 -40.984,20.384 ; -40.984,20.384 -40.79,20.578 ; -40.984,20.384 -40.984,20.578 ; -40.984,20.578 -40.79,20.578
  Bottom Layer w0.889: C11.2@-41.814,19.345 -41.814,16.59 v2@-41.753,16.528
  other v2: -41.677,16.401 -41.677,17.036
VBUS_PMIC: C1.2 C2.2 C3.2 C7.2 D1.K J3.A4 J3.A9 J3.B4 J3.B9 Q1.G R31.1 U1.5 U3.21 | length 64.1
  Top Layer w0.254: -57.943,20.297 -57.943,19.556 -57.969,19.531 -57.969,17.771 -57.754,17.556 U1.5@-57.142,17.556 ; C1.2@-57.918,20.66 -57.918,20.412 -57.918,20.393 -57.828,20.302 ; R31.1@-56.399,19.618 Q1.G@-56.399,20.449
  Top Layer w0.305: -63.043,19.882 -63.673,19.252 -63.673,15.692 -62.992,15.011 ; J3.A9@-62.172,14.95 -63.327,14.95 -63.927,15.549 -63.927,19.315 -63.192,20.05 J3.A4@-62.172,20.05 -61.065,20.05 -60.462,20.654 D1.K@-60.206,20.654 ; J3.B4@-62.172,15.25 -62.968,15.25 -63.5,15.782 -63.5,19.206 -62.932,19.774 -61.204,19.774 ; -61.296,19.867 -61.204,19.774 ; -61.22,20.107 D1.K@-60.616,20.711 ; -60.61,19.828 -60.026,20.412 D1.K@-60.006,20.432 ; -60.481,20.251 -60.957,19.774 ; -59.848,20.311 -60.603,19.556 -60.739,19.556 ; -61.204,19.774 -60.957,19.774 ; -61.204,19.774 -60.986,19.556 -60.739,19.556 ; -60.957,19.774 -60.739,19.556
  Top Layer w0.508: D1.K@-60.433,20.412 -60.026,20.412 -57.918,20.412 -57.226,20.412 ; D1.K@-60.407,20.742 C1.2@-57.918,20.742 ; C1.2@-57.918,20.66 C1.2@-57.918,20.742 ; -57.527,20.563 -57.145,20.563 -57.145,20.493 ; -57.506,20.742 C1.2@-57.918,20.742 ; -57.404,20.742 v2@-56.951,21.195 ; -57.145,20.432 -57.145,20.493 ; v2(-56.899,21.015) v2@-56.891,21.015 ; v2@-56.891,21.549 v2@-56.891,21.015 ; Q1.G@-56.439,20.563 v2@-56.891,21.015 ; Q1.G@-56.399,20.449 -57.048,20.449 -57.085,20.412 -57.226,20.412 ; -57.226,20.412 -57.145,20.493
  Bottom Layer w0.254: C7.2@-42.621,22.361 -42.182,21.922 -41.797,21.922 ; C7.2@-42.414,22.701 -41.895,22.701 -41.74,22.545 ; -41.993,22.47 -41.512,21.989 ; U3.21@-40.318,21.578 -40.773,21.578 -41.117,21.922 ; -41.797,21.922 -42.275,22.545 -42.209,22.545 -41.74,22.545 ; -41.797,21.922 -41.117,21.922 ; -41.74,22.545 -41.117,21.922
  Bottom Layer w0.889: v2@-56.899,21.135 v2(-56.899,21.549) -56.899,21.774 -56.119,22.554 -42.219,22.554 -42.209,22.545 -42.053,22.389
VBUSOUT: C8.2 R15.2 TP18.1 U3.22 | length 33.6
  Top Layer w0.254: v2(-55.646,15.58) -53.098,15.58 R15.2@-52.978,15.7
  Mid-Layer4 w0.254: v2(-55.646,15.58) -55.646,14.088 v3(-53.177,11.619)
  Mid-Layer2 w0.254: v2(-55.646,15.58) -54.356,16.87 -54.356,21.635 -53.543,22.448 -43.665,22.448 -43.267,22.846 -43.267,24.756 -42.832,25.191 -41.523,25.191 v2(-41.491,25.159)
  Bottom Layer w0.254: v2(-41.491,25.159) -41.509,25.141 -41.509,24.463 C8.2@-41.528,24.445 -41.521,24.439 -41.521,22.865 -40.734,22.078 U3.22@-40.318,22.078
VCOM0_CTS: U5.K8 U8.12 | length 7.6
  Top Layer w0.102: U5.K8@-49.5,22.112 -49.5,22.587 -49.397,22.691 -48.79,22.691 v1(-48.754,22.654) ; v1(-45.179,25.35) U8.12@-45.147,25.318
  Mid-Layer1 w0.102: v1(-48.754,22.654) -48.601,22.501 -45.656,22.501 -45.073,23.084 -45.073,25.245 v1(-45.179,25.35)
VCOM0_RTS: U5.K10 U8.8 | length 6
  Top Layer w0.102: U5.K10@-50.2,22.112 -50.2,22.631 -49.864,22.968 v1(-49.001,22.968) ; v1@-49.001,22.92 v1@-48.997,22.92
  Mid-Layer1 w0.102: v1(-49.001,22.968) -48.581,22.968 -48.352,22.739 -45.834,22.739 -45.366,23.207 v1(-45.366,23.461)
VCOM0_RXD: U5.K3 U8.4 | length 3.3
  Top Layer w0.089: v1(-47.956,23.032) -48.026,22.962 -48.026,22.388 U5.K3@-47.75,22.112 ; v1(-47.058,23.032) -47.058,23.994 -46.902,24.15 U8.4@-46.716,24.15
  Mid-Layer1 w0.102: v1(-47.956,23.032) v1(-47.058,23.032)
VCOM0_TXD: U5.E2 U8.16 | length 10.6
  Top Layer w0.127: U8.16@-46.547,25.919 v1(-46.546,25.92)
  Mid-Layer1 w0.102: v1@-47.399,20.363 v1(-47.4,20.362) -47.773,20.362 -48.045,20.634 -48.045,20.86 -48.411,21.226 -48.411,22.007 -48.148,22.27 -45.564,22.27 -44.825,23.009 -44.825,23.231 -44.822,23.234 -44.822,25.407 -45.335,25.92 v1(-46.546,25.92)
VCOM1_CTS: U5.J4 U9.9 | length 16.9
  Mid-Layer1 w0.102: v1(-48.1,21.762) -48.1,21.912 -47.959,22.054 -47.39,22.054 -47.204,21.868 -41.557,21.868 -40.211,20.522 -40.211,17.081 -38.633,15.503 -36.97,15.503 v1(-36.37,16.103)
VCOM1_RTS: U5.J5 U9.13 | length 17.5
  Top Layer w0.089: U5.J5@-48.45,21.762 -48.45,21.579 -48.252,21.381 v1(-48.1,21.381)
  Mid-Layer1 w0.102: v1(-48.1,21.381) -41.716,21.381 -40.673,20.337 -40.673,16.891 -38.749,14.967 -36.687,14.967 -36.146,14.427 v1(-36.144,14.427)
VCOM1_RXD: U5.J3 U9.1 | length 17.6
  Mid-Layer1 w0.102: v1(-47.75,21.762) -47.623,21.635 -41.647,21.635 -40.444,20.432 -40.444,16.991 -38.649,15.196 -36.165,15.196 -35.872,14.904 v1(-35.021,14.904)
VCOM1_TXD: U5.F3 U9.5 | length 17.1
  Top Layer w0.089: v1(-34.938,16.567) U9.5@-34.938,16.677 U9.5@-34.938,16.708
  Top Layer w0.102: v1(-40.965,17.815) v1(-39.918,17.207)
  Mid-Layer1 w0.102: v1(-47.75,20.712) -47.315,21.148 -41.807,21.148 -40.965,20.307 v1(-40.965,17.815) ; v1(-39.918,17.207) -38.443,15.732 -37.189,15.732 -36.526,16.395 -36.247,16.395 -36.004,16.395 -35.11,16.395 v1(-34.938,16.567)
VDD_DBGR: C13.2 C22.2 C23.2 C24.2 C25.2 C28.2 C29.2 C30.2 C31.2 J4.1 L2.2 R30.2 R35.1 R60.2 TP17.1 U3.32 U5.A3 U5.B7 U5.B10 U5.B12 U5.D2 U5.E11 U5.H11 U5.K1 U5.L5 U5.L11 | length 87.5
  Top Layer w0.102: -50.828,21.69 U5.H11@-50.55,21.412 ; C31.2@-50.589,17.758 -50.589,18.204 -50.2,18.593 U5.B10@-50.2,19.312 ; U5.B7@-49.15,19.312 -48.938,19.1 -48.938,18.045 ; -47.424,22.486 U5.K1@-47.05,22.112 ; U5.D2@-47.4,20.012 -46.969,20.444 -46.457,20.444 -46.325,20.575 v1(-46.122,20.575)
  Top Layer w0.127: v1(-51.937,21.876) -51.014,21.876 -50.828,21.69 ; R60.2@-51.098,23.379 -51.079,23.361 v1(-50.303,23.361) -50.303,22.964 -50.55,22.716 U5.L11@-50.55,22.462 ; v1(-49.188,16.496) -48.974,16.71 -48.974,18.009 -48.938,18.045 ; v1(-48.969,23.356) -48.939,23.356 -48.45,22.868 U5.L5@-48.45,22.462 ; R30.2@-48.082,24.637 -47.905,24.637 -47.639,24.371 -47.639,23.661 -47.821,23.479 ; U5.A3@-47.75,18.962 -47.647,18.859 -47.647,18.317 -47.336,18.006 C22.2@-47.336,17.758
  Top Layer w0.203: -52.756,13.877 -52.741,13.893 R35.1@-52.741,14.487 ; C24.2@-48.071,23.43 C24.2@-48.064,23.43 ; v1(-48.071,23.479) -47.821,23.479 -47.456,23.115 -47.456,22.524
  Top Layer w0.305: v2(-58.944,6.995) -58.928,7.011 J4.1@-58.928,7.917 ; v2(-58.392,10.252) -58.379,10.252 -54.754,13.877 -52.756,13.877 -47.404,13.877 -47.142,14.139 v2(-47.142,14.767)
  Mid-Layer1 w0.203: v1(-51.937,21.876) -51.102,21.042 -49.721,21.042 ; v1(-50.9,19.312) -50.9,19.567 -50.663,19.804 -49.723,19.804 ; v1(-50.589,17.655) -50.326,17.655 -49.08,18.902 -48.74,18.902 ; v1(-50.55,20.362) -49.723,20.362 ; v1(-50.303,23.361) -49.693,23.361 -49.414,23.64 -49.115,23.64 -49.113,23.637 -48.828,23.637 -48.825,23.64 -48.232,23.64 v1(-48.071,23.479) ; -49.721,23.14 -49.696,23.14 -49.48,23.356 v1(-48.969,23.356) ; v1(-49.188,16.496) -48.474,16.496 -48.417,16.439 ; -48.417,17.699 v1(-47.277,17.699) ; -48.417,18.281 v1(-46.122,20.575)
  Mid-Layer1 w0.305: v2@-37.975,16.146 -37.975,17.42 -35.528,19.867 v2(-35.528,23.811)
  Mid-Layer1 w0.508: -49.724,20.809 -49.723,20.848 ; -49.723,20.861 -49.723,20.848 ; -49.696,23.205 -49.696,23.14 -49.721,21.042 -49.723,20.848 ; -49.092,19.254 -49.723,19.885 -49.723,20.362 -49.723,20.848 ; -49.063,19.225 -48.74,18.902 -48.417,18.579 -48.417,18.281 -48.417,17.699 -48.417,16.439 -48.411,16.433 ; -48.411,17.247 -48.411,16.433 ; v2(-47.142,14.767) -47.86,14.767 -48.411,15.317 -48.411,16.433
  Mid-Layer2 w0.305: v2(-58.944,6.995) -58.944,9.7 v2(-58.392,10.252)
  Bottom Layer w0.305: U3.32@-36.044,23.794 -36.01,23.828 -35.545,23.828 v2(-35.528,23.811)
  Bottom Layer w0.508: v2(-47.142,14.767) -39.306,14.767 -37.955,16.117 v2@-37.927,16.117
  Bottom Layer w0.762: v2@-37.927,16.117 -33.803,16.117 -32.405,17.515 C13.2@-32.405,17.952 -32.454,18.001 L2.2@-32.454,19.421
  other v2: -37.968,16.22
VDD_nRF54: C40.2 C41.2 C42.2 C43.2 C44.2 C58.2 D3.K P3.2 R17.2 R19.2 R21.1 U6.10 U6.22 U6.36 U6.47 U6.48 U7.8 | length 109.8
  Top Layer w0.254: R17.2@-55.792,23.98 -55.767,24.006 v1(-55.767,25.85) ; v1(-38.041,30.788) -38.041,31.906 -37.375,32.572 -34.698,32.572 -34.46,32.81 P3.2@-34.46,33.735 ; R21.1@-37.342,16.451 v1(-36.944,16.85) ; C58.2@-29.1,28.185 C58.2@-28.991,28.185 ; v2@-28.541,28.493 -28.722,28.493 -28.991,28.225 C58.2@-28.991,28.185 ; U7.8@-27.739,28.135 -27.865,28.009 -28.814,28.009 C58.2@-28.991,28.185
  Mid-Layer1 w0.254: v1(-55.767,25.85) -55.767,26.517 -51.378,30.906 -38.159,30.906 v1(-38.041,30.788) ; v1(-36.944,16.85) -36.737,17.057 -35.972,17.057 -35.922,17.006 -35.38,17.006 -35.196,17.19 -31.1,17.19 -30.707,17.583 -30.707,23.216 -30.379,23.544 -30.379,26.63 -28.541,28.468 v2@-28.541,28.493
  Mid-Layer4 w0.508: P3.2@-34.46,33.735 -34.46,33.639 -32.81,31.989 -25.217,31.989 -24.419,32.787 -20.972,32.787 v3(-19.828,31.642)
  Mid-Layer2 w0.635: P3.2@-34.46,33.735 -34.46,32.773 -33.753,32.066 -29.681,32.066 -28.541,30.926 -28.541,28.493 -24.072,24.024 v2(-24.072,20.725) -22.737,19.39 -18.662,19.39 v2(-17.502,20.55)
  Bottom Layer w0.254: v3(-25.407,32.074) -25.407,28.51 -25.135,28.237 U6.10@-24.167,28.237 ; C44.2@-24.226,23.228 -23.774,23.228 ; C44.2@-24.157,23.018 -23.804,23.018 ; -24.055,23.003 -23.702,23.003 -23.645,23.06 ; U6.48@-23.387,23.857 -23.387,23.616 -23.774,23.228 ; U6.47@-22.987,23.857 -22.987,23.457 -23.248,23.457 -23.645,23.06 ; v3(-19.828,31.642) -19.787,31.601 C41.2@-19.787,30.934 ; C41.2@-19.806,30.953 C41.2@-19.787,30.934 ; U6.22@-19.787,29.817 C41.2@-19.787,30.934 ; U6.36@-18.207,24.593 -18.207,22.528 C42.2@-18.257,22.478 -18.234,22.455 -18.075,22.455 -17.738,22.118 -17.738,21.257 -17.502,21.021 v2(-17.502,20.55) ; -23.774,23.228 -23.794,23.208 -23.645,23.06
  Bottom Layer w0.508: C44.2@-24.157,23.018 -24.157,22.359 -24.157,20.81 v2(-24.072,20.725)
  other v2: -28.575,28.566
VDD_nRF93: C59.2 C60.2 C61.2 C62.2 C63.2 C64.2 D5.K P4.2 U11.42 U11.43 | length 59.2
  Top Layer w0.508: U11.42@-12.707,20.679 -11.995,20.679 -11.76,20.914 v2(-11.76,20.947) -11.735,20.972 v2(-11.735,21.498) -12.016,21.779 U11.43@-12.707,21.779 ; U11.42@-12.243,20.716 -12.085,20.874 -12.085,21.591
  Mid-Layer2 w1.016: P4.2@-34.46,1.5 -32.245,3.715 -25.932,3.715 ; -25.939,3.708 -25.932,3.715 ; -16.753,12.44 -17.207,12.44 -25.932,3.715
  Bottom Layer w0.203: C59.2@-13.46,19.312 -12.737,20.034 -12.737,21.052 C64.2@-12.737,22.361 ; C59.2@-13.175,19.368 -12.737,19.806
  Bottom Layer w0.254: D5.K@-15.291,14.462 -14.74,14.462 ; -12.556,19.935 -12.537,19.916 -12.426,19.805 -12.294,19.673 ; -12.433,20.716 -12.294,20.577 ; -12.3,20.848 -12.294,20.848 ; -12.294,21.661 -12.294,20.848 ; -12.268,21.218 -12.009,21.478 ; -12.243,21.066 v2@-11.92,21.389 ; -12.212,20.746 -12.141,20.817 ; -12.192,21.661 -12.009,21.478 ; -12.167,19.546 -12.294,19.673 ; -12.141,20.266 -12.141,20.424 ; -12.141,21.777 v2@-11.925,21.561 ; -12.136,19.524 -12.136,19.57 -12.136,20.096 -12.136,20.419 -12.141,20.424 ; v2@-11.878,21.608 v2@-11.925,21.561 ; v2@-11.853,21.456 v2@-11.92,21.389 ; v2@-11.822,21.136 -12.11,20.848 ; v2@-11.802,21.272 v2@-11.92,21.389 ; v2@-11.751,21.387 -11.76,21.396 v2@-11.925,21.561 ; v2@-11.749,20.848 -11.76,20.848 -12.11,20.848 ; -12.294,19.673 -12.294,19.938 -12.294,20.577 ; -12.294,20.577 -12.294,20.848 ; -12.294,20.577 -12.141,20.424 ; -12.294,20.848 -12.11,20.848 ; -12.141,20.424 -12.141,20.817 ; -12.141,20.817 -12.11,20.848 ; -12.009,21.478 v2@-11.925,21.561 ; -12.009,21.478 v2@-11.92,21.389
  Bottom Layer w0.5: C59.2@-13.495,18.737 -13.019,19.212 -12.582,19.65 -12.426,19.805 -12.294,19.938 -12.136,20.096 -11.76,20.471 ; C59.2@-12.991,18.715 -12.136,19.57 -11.76,19.946 -11.76,20.471 ; -12.537,19.916 -12.537,21.052 -12.537,22.164 -12.466,22.234 -11.892,22.234 -11.76,22.103 -11.76,21.396 v2(-11.76,20.947) -11.76,20.848 -11.76,20.471 ; -12.268,21.854 -12.082,21.854 ; -12.021,20.071 -12.021,21.183
  Bottom Layer w1.016: v2(-17.101,12.549) -17.072,12.578 v2(-16.543,12.578) -16.307,12.578 -15.1,13.785 -15.1,13.806 -14.592,14.314 ; -14.599,14.322 -13.892,15.029 C60.2@-13.342,15.579 ; C60.2@-13.6,16.099 C59.2@-13.6,18.715 ; C60.2@-13.441,15.865 C59.2@-13.441,18.481
VSYS: C9.2 C10.2 C17.2 C18.2 P1.2 R2.1 R3.1 R6.2 U3.4 U3.20 U4.3 | length 97.7
  Top Layer w0.203: -32.697,7.978 -32.575,7.978
  Top Layer w0.254: v2(-52.772,27.341) -52.772,28.243 -52.756,28.258 -52.808,28.31 R3.1@-52.717,28.402 -52.736,28.421 R2.1@-52.736,30.3
  Top Layer w0.508: C17.2@-33.467,8.899 -33.467,9.405 v2(-33.301,9.57) v2@-32.819,9.57 ; C17.2@-33.225,9.189 -32.738,9.189 ; -33.2,8.85 C18.2@-32.712,8.85 ; -33.062,8.718 -32.717,8.374 ; v2@-32.814,9.57 v2@-32.819,9.57 ; -32.697,7.375 -32.697,7.978 C18.2@-32.697,8.829 ; -32.621,7.299 -32.474,7.446 C18.2@-32.474,8.899 -32.474,9.225 v2@-32.819,9.57
  Mid-Layer4 w0.254: v2(-52.772,27.341) v4(-39.599,27.341)
  Mid-Layer2 w0.254: -40.318,19.267 -40.276,19.309 v2(-40.276,24.912) ; -33.15,9.316 -32.702,9.316 -32.527,9.491 -32.527,9.706 -32.72,9.899
  Mid-Layer2 w0.305: P1.2@-59.735,1.5 -58.06,3.175 -55.033,3.175 -47.204,11.005 -33.295,11.005 -33.178,11.122
  Mid-Layer2 w0.508: -42.55,19.307 -42.55,20.445 -42.503,20.493 v2@-42.024,20.493 ; v2@-42.012,20.461 v2(-42.012,20.389) -42.012,19.92 -41.673,19.581
  Mid-Layer2 w1.016: -42.257,20.238 -42.257,19.267 -40.318,19.267 -33.58,19.267 ; -33.178,19.514 -33.178,18.865 ; -33.121,20.42 -33.121,19.726 -33.58,19.267 ; -33.011,9.57 -33.178,9.737 -33.178,11.122 -33.178,18.865 ; -33.58,19.267 -33.178,18.865
  Bottom Layer w0.254: -41.984,21.392 -41.347,21.392 -41.033,21.078 ; -41.615,20.786 -41.324,20.786 -41.033,21.078 ; U3.20@-40.318,21.078 -41.033,21.078 ; v2(-40.276,24.912) -39.941,24.912 R6.2@-39.628,25.225 ; R6.2@-39.66,25.257 -39.55,25.368 -39.645,25.463 -39.599,25.509 v4(-39.599,27.341) ; U3.4@-35.318,21.578 -34.578,21.578 ; -33.854,21.024 -34.025,21.024 -34.578,21.578 ; C9.2@-33.838,21.578 -34.578,21.578
  Bottom Layer w0.508: v2(-42.573,20.389) v2@-42.55,20.389 ; C10.2@-42.55,20.951 v2@-42.55,20.389 ; C10.2@-42.159,20.744 -41.844,21.059 -41.317,21.059 ; -41.615,20.786 v2(-42.012,20.389) v2@-42.55,20.389 ; -34.228,21.457 C9.2@-33.527,21.457 ; -33.854,21.024 v2@-33.367,20.537 ; C9.2@-33.2,20.937 v2(-32.798,20.536) v2@-33.366,20.536 ; v2@-33.367,20.537 v2@-33.366,20.536
  other v2: -32.754,9.57 -33.368,20.536
X1: C57.2 U5.A1 X1.1 | length 2.2
  Top Layer w0.127: U5.A1@-47.05,18.962 -46.678,18.59 -45.102,18.59 X1.1@-45.017,18.675
X2: C79.1 U5.A2 X1.3 | length 4.4
  Top Layer w0.127: U5.A2@-47.4,18.962 -46.8,18.362 -46.43,18.362 -46.047,17.979 C79.1@-45.987,17.979 -44.082,17.979 -43.867,17.764 X1.3@-43.867,17.391
XC1: C38.2 U6.34 X2.1 | length 5.4
  Bottom Layer w0.127: U6.34@-18.207,25.437 -17.657,25.437 -16.609,24.389 -16.116,24.389 -16.042,24.315 C38.2@-16.042,24.023 -16.172,23.893 -16.172,22.544 -15.878,22.249 -15.807,22.249 X2.1@-15.471,21.913
XC2: C39.1 U6.35 X2.3 | length 3.1
  Bottom Layer w0.127: U6.35@-18.207,25.037 -17.616,25.037 -16.762,24.183 -16.762,24.108 C39.1@-16.676,24.021 -16.676,23.308 X2.3@-16.92,23.063
pads on no net: D1. D2. D3. D4. D5. D6. J1.0 J2.0@-56.743,19.857 J2.0@-60.767,14.777 J2.0@-60.767,17.317 J2.0@-60.767,19.857 J2.0@-66.742,14.777 J2.0@-66.742,17.317 J2.0@-66.743,19.857 J2.6 J3.A8 J3.B8 J4.0 J4.6 J4.7 J4.8 J4.9 J5.A8 J5.B8 LED4. Q1. Q2. Q3. Q4. Q5. Q6. Q7. Q8. U3. U3.8 U3.9 U3.10 U3.11 U3.15 U3.27 U3.30 U3.31 U4. U5.C4 U5.C5 U5.C6 U5.C7 U5.C8 U5.C9 U5.C10 U5.D1 U5.D10 U5.D11 U5.E3 U5.E4 U5.E10 U5.F10 U5.G3 U5.G10 U5.G11 U5.H1 U5.H2 U5.H3 U5.H10 U5.J2 U5.J6 U5.J7 U5.J8 U5.J9 U5.J10 U5.J11 U5.K2 U5.K4 U5.K5 U5.K7 U5.K9 U5.K12 U5.L1 U5.L3 U5.L7 U5.L9 U5.L12 U6. U7. U8.1 U8.5 U8.9 U8.13 U10.1 U10.5 U10.9 U10.11 U10.12 U10.13 U11.0 U11.21 U11.57 U11.58 U11.103 U13.0 U13.2 U13.4 U13.5 U13.8@-22.651,15.842 U13.9 X1. X2.

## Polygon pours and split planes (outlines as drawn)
GND on Top Layer "G2-GND" (solid, remove dead copper, pour order 46): -15.293,35 -70,35 -70,-0.006 0,-0.006 0,29.293 -15.293,29.293
GND on Top Layer "NONET_L-01_P-001" (hatched Horizontal grid 0.127 track 0.127, remove dead copper, pour order 48): -43.988,8.887 -43.983,8.882 -41.605,8.882 -40.878,8.155 -40.878,6.714 -41.338,6.254 -44.247,6.254 -44.498,6.505 -44.367,6.636 -44.367,8.344
GND on Mid-Layer2 "G2-GND" (solid, remove dead copper, pour order 40): -15.293,35 -70,35 -70,-0.006 0,-0.006 0,29.293 -15.293,29.293
GND on Mid-Layer3 "G2-GND" (solid, remove dead copper, pour order 38): -15.293,35 -70,35 -70,-0.006 0,-0.006 0,29.293 -15.293,29.293
GND on Bottom Layer "G2-GND" (hatched Horizontal grid 0.127 track 0.127, remove dead copper, pour order 34): -15.293,35 -70,35 -70,-0.006 0,-0.006 0,29.23 -15.293,29.23
GND on Mid-Layer1 "G2-GND" (solid, remove dead copper, pour order 44): -15.293,35 -70,35 -70,-0.006 0,-0.006 0,29.293 -15.293,29.293
GND on Mid-Layer4 "G2-GND" (solid, remove dead copper, pour order 36): -15.293,35 -70,35 -70,-0.006 0,-0.006 0,29.293 -15.293,29.293

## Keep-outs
Keep-Out Layer:
  lines w0.15: -69.195,13.844 -69.195,21 -69.195,28.156 ccw(c-70.195,28.156) -69.488,28.863 -69.707,29.082 cw(c-69,29.789) -70,29.789 -70,32.46 cw(c-67.46,32.46) -67.46,35 -1.3,35 cw(c-1.3,33.7) 0,33.7 0,1.3 cw(c-1.3,1.3) -1.3,0 -67.46,0 cw(c-67.46,2.54) -70,2.54 -70,5.211 cw(c-69,5.211) -69.707,5.918 -69.488,6.137 ccw(c-70.195,6.844) -69.195,6.844 -69.195,15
